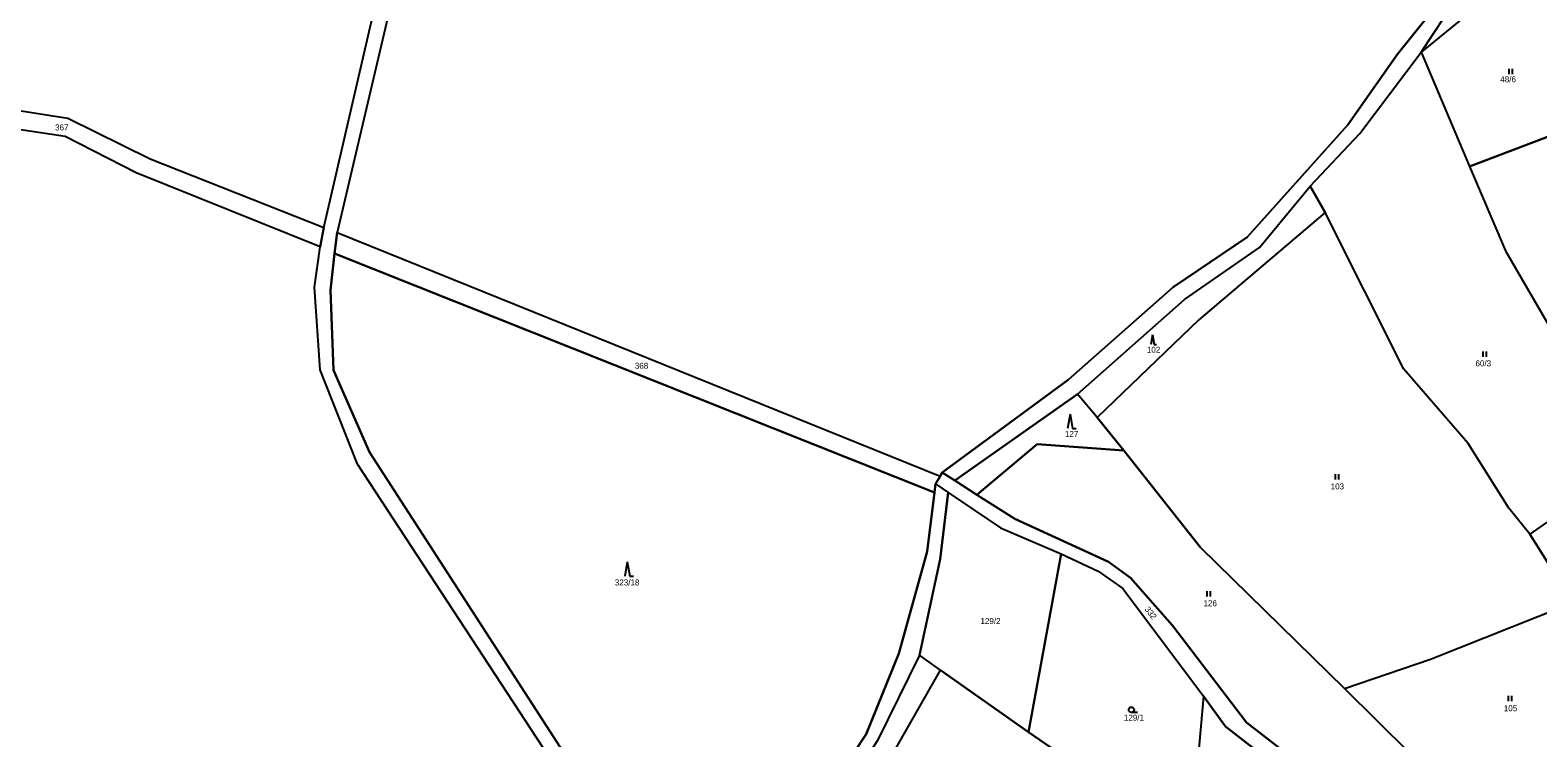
# Model space of a CAD drawing. Extents: x -590606 to -587796, y -1065936 to -1062515.
# Drawn here: x -589413.2 to -588986.8, y -1063876.9 to -1063676.6 of the extents above; entities that cross this region are included whole.
import ezdxf

# ---------------------------------------------------------------- set-up
doc = ezdxf.new("R2010")
doc.units = 0
doc.layers.add('Parcela nároku', color=7, linetype='Continuous')
doc.layers.add('Vrstva 30', color=7, linetype='Continuous')

msp = doc.modelspace()

# ---------------------------------------------------------------- linework, layer by layer
at = {"layer": 'Parcela nároku'}
for points in [[(-589421.81, -1063664.72), (-589435.4, -1063674.78), (-589450.59, -1063695.28), (-589432.57, -1063696.77), (-589402.5, -1063701.5), (-589379.22, -1063713.03), (-589330.1, -1063732.43), (-589312.33, -1063655.31), (-589317.18, -1063632.47), (-589308.41, -1063617.86), (-589285.34, -1063599.17), (-589303.4, -1063600.75), (-589385.85, -1063650.59), (-589405.06, -1063656.37)], [(-589019.8, -1063682.85), (-589009.72, -1063667.49), (-589000.64, -1063658), (-588990.25, -1063650.35), (-588988.07, -1063656.88)], [(-588967.9, -1063700.67), (-588977.28, -1063682.45), (-588988.07, -1063656.88), (-589019.8, -1063682.85), (-589006.06, -1063715.24)], [(-589006.06, -1063715.24), (-588995.94, -1063739.11), (-588960.84, -1063799.54), (-588989.02, -1063819.29), (-588994.94, -1063811.86), (-589006.48, -1063793.6), (-589024.66, -1063772.58), (-589046.9, -1063728.25), (-589051.16, -1063720.8), (-589037.08, -1063705.89), (-589019.8, -1063682.85)], [(-589379.22, -1063713.03), (-589330.1, -1063732.43), (-589331.14, -1063737.89), (-589383.17, -1063717.01), (-589403.24, -1063706.74), (-589431.69, -1063702.42), (-589453.24, -1063701.5), (-589450.59, -1063695.28), (-589432.57, -1063696.77), (-589402.5, -1063701.5)], [(-588930.68, -1063779.51), (-588937.25, -1063766.73), (-588950.98, -1063737.57), (-588960.87, -1063714.33), (-588967.9, -1063700.67), (-589006.06, -1063715.24), (-588995.94, -1063739.11), (-588960.84, -1063799.54)], [(-589051.16, -1063720.8), (-589046.9, -1063728.25), (-589082.61, -1063758.61), (-589111.45, -1063786.24), (-589116.97, -1063779.65), (-589086.69, -1063752.83), (-589065.46, -1063738.1)], [(-589082.61, -1063758.61), (-589111.45, -1063786.24), (-589103.91, -1063795.61), (-589082.22, -1063823.01), (-589041.47, -1063862.89), (-589017.13, -1063854.66), (-588978.91, -1063839.48), (-588976.89, -1063838.59), (-588989.02, -1063819.29), (-588994.94, -1063811.86), (-589006.48, -1063793.6), (-589024.66, -1063772.58), (-589046.9, -1063728.25)], [(-589326.33, -1063733.9), (-589155.85, -1063802.8), (-589157.1, -1063805.04), (-589157.4, -1063807.44), (-589327.09, -1063739.85)], [(-589327.09, -1063739.85), (-589157.4, -1063807.44), (-589159.46, -1063824.12), (-589167.48, -1063852.98), (-589176.77, -1063875.88), (-589203.59, -1063916.55), (-589217.17, -1063943.01), (-589223.79, -1063961.26), (-589256.24, -1063890.49), (-589317.19, -1063796.08), (-589327.35, -1063772.85), (-589328.28, -1063750.21)], [(-589116.97, -1063779.65), (-589151.67, -1063804.1), (-589145.4, -1063808.11), (-589128.36, -1063793.8), (-589103.91, -1063795.61), (-589111.45, -1063786.24)], [(-589128.36, -1063793.8), (-589145.4, -1063808.11), (-589134.69, -1063814.94), (-589108.21, -1063827.09), (-589102.02, -1063831.62), (-589090.13, -1063845.11), (-589069.14, -1063872.51), (-589053.21, -1063884.95), (-589028.49, -1063889.47), (-589013.53, -1063890.56), (-589041.47, -1063862.89), (-589082.22, -1063823.01), (-589103.91, -1063795.61)], [(-588949.5, -1063812.6), (-588960.84, -1063799.54), (-588989.02, -1063819.29), (-588976.89, -1063838.59), (-588971.47, -1063846.51), (-588940.17, -1063826.84)], [(-589155.77, -1063826.35), (-589153.54, -1063807.45), (-589138.7, -1063817.48), (-589121.59, -1063824.84), (-589130.81, -1063875.25), (-589155.67, -1063857.74), (-589161.69, -1063853.54)], [(-589111.09, -1063829.69), (-589104.16, -1063834.59), (-589081.3, -1063865.14), (-589085.38, -1063910.66), (-589110.75, -1063889.1), (-589116.38, -1063885.17), (-589130.81, -1063875.25), (-589121.59, -1063824.84)], [(-588969.91, -1063849.07), (-588968.27, -1063851.78), (-588958.1, -1063870.25), (-588952.08, -1063879.66), (-588956.54, -1063883.07), (-588968.03, -1063870.31), (-588977.4, -1063878.2), (-588978.32, -1063877.14), (-588983.46, -1063885.54), (-589013.53, -1063890.56), (-589041.47, -1063862.89), (-589017.13, -1063854.66), (-588978.91, -1063839.48), (-588976.89, -1063838.59), (-588971.47, -1063846.51)], [(-589161.69, -1063853.54), (-589173.52, -1063877.63), (-589193.54, -1063908.46), (-589187.09, -1063912.76), (-589185.12, -1063909.31), (-589155.67, -1063857.74)], [(-589185.12, -1063909.31), (-589155.67, -1063857.74), (-589130.81, -1063875.25), (-589116.38, -1063885.17), (-589116.56, -1063887.54), (-589074.59, -1063924.4), (-589104.36, -1063968.29), (-589115.33, -1063959.3), (-589127.03, -1063949.71), (-589143.54, -1063936.18)], [(-589081.3, -1063865.14), (-589085.38, -1063910.66), (-589064.92, -1063932.16), (-589031.97, -1063971.35), (-589026.08, -1063966.87), (-589035.68, -1063956.44), (-589059.79, -1063917.68), (-589060.17, -1063885.31), (-589075.07, -1063873.65)]]:
    msp.add_lwpolyline(points, close=True, dxfattribs=at)
for points in [[(-589307.9, -1063655.2), (-589326.33, -1063733.9), (-589327.09, -1063739.85), (-589328.28, -1063750.21), (-589327.35, -1063772.85), (-589317.19, -1063796.08), (-589256.24, -1063890.49), (-589223.79, -1063961.26), (-589228.02, -1063972.63), (-589228.02, -1063961.61), (-589262.9, -1063887.63), (-589320.58, -1063799.46), (-589331.2, -1063772.73), (-589332.78, -1063749.35), (-589331.14, -1063737.89), (-589330.1, -1063732.43), (-589312.33, -1063655.31)], [(-589307.9, -1063655.2), (-589326.33, -1063733.9), (-589155.85, -1063802.8), (-589155.29, -1063801.79), (-589119.62, -1063775.61), (-589089.88, -1063749.38), (-589069.02, -1063735.21), (-589040.47, -1063703.41), (-589026.46, -1063683.36), (-589006.02, -1063657.87)], [(-589006.02, -1063657.87), (-589026.46, -1063683.36), (-589040.47, -1063703.41), (-589069.02, -1063735.21), (-589089.88, -1063749.38), (-589119.62, -1063775.61), (-589155.29, -1063801.79), (-589151.67, -1063804.1), (-589116.97, -1063779.65), (-589086.69, -1063752.83), (-589065.46, -1063738.1), (-589051.16, -1063720.8), (-589037.08, -1063705.89), (-589019.8, -1063682.85), (-589009.72, -1063667.49)], [(-589415.32, -1064168.15), (-589348.65, -1064220.94), (-589342.52, -1064231.73), (-589341.32, -1064229.23), (-589330.47, -1064221.55), (-589321.03, -1064204.69), (-589297.69, -1064139.02), (-589287.98, -1064118.63), (-589265.69, -1064040.57), (-589246.35, -1064004.19), (-589234.85, -1063987.83), (-589228.02, -1063972.63), (-589228.02, -1063961.61), (-589262.9, -1063887.63), (-589320.58, -1063799.46), (-589331.2, -1063772.73), (-589332.78, -1063749.35), (-589331.14, -1063737.89), (-589383.17, -1063717.01), (-589403.24, -1063706.74), (-589431.69, -1063702.42)], [(-589203.59, -1063916.55), (-589176.77, -1063875.88), (-589167.48, -1063852.98), (-589159.46, -1063824.12), (-589157.4, -1063807.44), (-589157.1, -1063805.04), (-589153.54, -1063807.45), (-589155.77, -1063826.35), (-589161.69, -1063853.54), (-589173.52, -1063877.63)], [(-589053.21, -1063884.95), (-589069.14, -1063872.51), (-589090.13, -1063845.11), (-589102.02, -1063831.62), (-589108.21, -1063827.09), (-589134.69, -1063814.94), (-589145.4, -1063808.11), (-589151.67, -1063804.1), (-589155.29, -1063801.79), (-589155.85, -1063802.8), (-589157.1, -1063805.04), (-589153.54, -1063807.45), (-589138.7, -1063817.48), (-589121.59, -1063824.84), (-589111.09, -1063829.69), (-589104.16, -1063834.59), (-589081.3, -1063865.14), (-589075.07, -1063873.65), (-589060.17, -1063885.31)]]:
    msp.add_lwpolyline(points, dxfattribs=at)
at = {"layer": 'Vrstva 30'}
for p, q in [((-588994.99, -1063687.52), (-588994.99, -1063689.02)), ((-588993.96, -1063689.02), (-588993.96, -1063687.52)), ((-589095.74, -1063762.85), (-589096.24, -1063765.53)), ((-589095.74, -1063762.85), (-589095.25, -1063765.53)), ((-589095.25, -1063765.53), (-589094.58, -1063765.53)), ((-589002.29, -1063767.54), (-589002.29, -1063769.04)), ((-589001.27, -1063769.04), (-589001.27, -1063767.54)), ((-589119.07, -1063785.31), (-589119.81, -1063789.31)), ((-589119.07, -1063785.31), (-589118.34, -1063789.31)), ((-589118.34, -1063789.31), (-589117.34, -1063789.31)), ((-589044.11, -1063802.26), (-589044.11, -1063803.76)), ((-589043.08, -1063803.76), (-589043.08, -1063802.26)), ((-589244.29, -1063827.1), (-589245.03, -1063831.1)), ((-589244.29, -1063827.1), (-589243.56, -1063831.1)), ((-589243.56, -1063831.1), (-589242.56, -1063831.1)), ((-589080.41, -1063835.4), (-589080.41, -1063836.9)), ((-589079.39, -1063836.9), (-589079.39, -1063835.4)), ((-588995.19, -1063865), (-588995.19, -1063866.5)), ((-588994.17, -1063866.5), (-588994.17, -1063865)), ((-589099.97, -1063869.69), (-589101.72, -1063869.69))]:
    msp.add_line(p, q, dxfattribs=at)
msp.add_circle((-589101.72, -1063868.94), 0.75, dxfattribs=at)

# ---------------------------------------------------------------- texts
at = {"layer": 'Parcela nároku'}
for s, p in [('48/6', (-588997.39, -1063691.37)), ('367', (-589406.14, -1063704.99)), ('102', (-589097.35, -1063767.92)), ('368', (-589242.16, -1063772.44)), ('60/3', (-589004.42, -1063771.76)), ('127', (-589120.53, -1063791.74)), ('103', (-589045.37, -1063806.59)), ('323/18', (-589247.81, -1063833.77)), ('126', (-589081.34, -1063839.66)), ('129/2', (-589144.42, -1063844.69)), ('105', (-588996.41, -1063869.37)), ('129/1', (-589103.86, -1063872.03))]:
    msp.add_text(s, height=1.7, dxfattribs=at).set_placement(p)
msp.add_text('332', height=1.7, rotation=307.6113, dxfattribs=at).set_placement((-589098.09, -1063840.55))

doc.saveas('drawing.dxf')
